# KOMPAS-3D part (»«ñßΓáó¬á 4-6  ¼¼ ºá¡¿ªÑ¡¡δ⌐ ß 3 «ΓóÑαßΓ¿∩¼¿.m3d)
File: created 10.02.2016 13:21:24, last saved 24.07.2016 08:51:11.
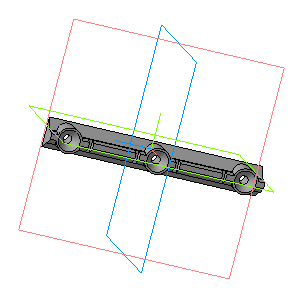
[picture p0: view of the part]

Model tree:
1. Эскиз:1
2. Операция выдавливания:1
     Расстояние 1 = 25.3; Расстояние 2 = 25.3
3. Эскиз:2
4. Вырезать элемент выдавливания:1
     Расстояние 1 = 2.5
5. Эскиз:3
6. Вырезать элемент выдавливания:2
     Расстояние 1 = 60
7. Эскиз:4
8. Операция выдавливания:2
     Расстояние 1 = 10; Расстояние 2 = 7.5
9. Эскиз:5
10. Вырезать элемент выдавливания:3
     Расстояние 1 = 50
11. Эскиз:6
12. Вырезать элемент выдавливания:4
     Расстояние 1 = 3; Угол 1 = 32
13. Скругление:3
     Радиус = 1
